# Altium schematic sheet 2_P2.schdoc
size 431 x 309 mm; Symbol: Sheet-Symbol_A3; Device: Sheet-Symbol_A3; @Page Name: P2; @Create Date: 2022-12-06; @Page Count: 3; @Page No: 2; @Project Name: MainBoard; @Schematic Name: Schematic1; @Update Date: 2022-12-29 15:32:21; Company: 嘉立创EDA; Page Size: A3; Version: V1.0
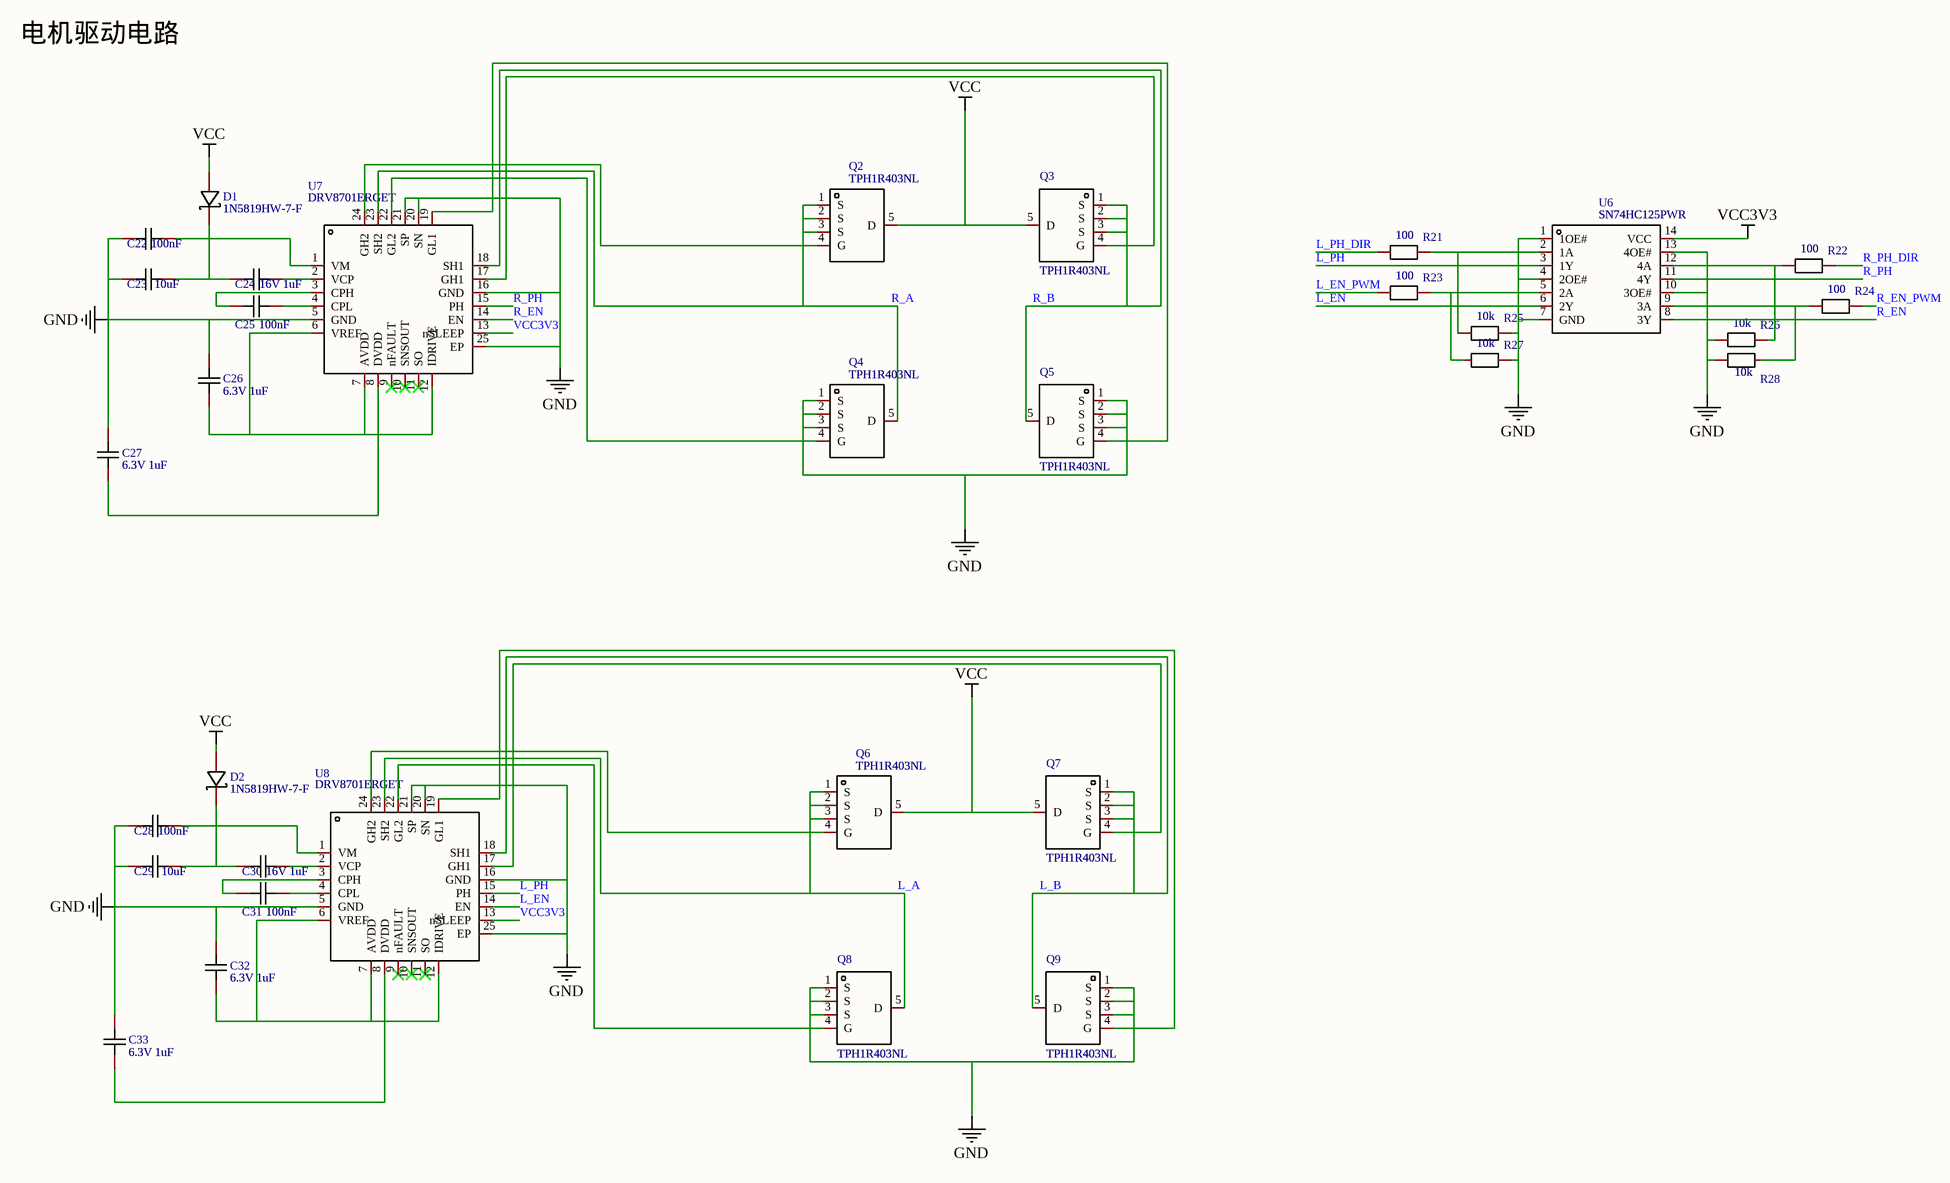
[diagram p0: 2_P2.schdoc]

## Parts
C22  100nF  [C0603]
C23  10uF  [C0603]
C24  16V 1uF  [C0603]
C25  100nF  [C0603]
C26  6.3V 1uF  [C0603]
C27  6.3V 1uF  [C0603]
C28  100nF  [C0603]
C29  10uF  [C0603]
C30  16V 1uF  [C0603]
C31  100nF  [C0603]
C32  6.3V 1uF  [C0603]
C33  6.3V 1uF  [C0603]
D1  1N5819HW-7-F  [SOD-123_L2.8-W1.8-LS3.7-FD]
D2  1N5819HW-7-F  [SOD-123_L2.8-W1.8-LS3.7-FD]
Q2  TPH1R403NL  [POWERVDFN-8_L6.2-W5.2-P1.27-LS6.0-BL]
Q3  TPH1R403NL  [POWERVDFN-8_L6.2-W5.2-P1.27-LS6.0-BL]
Q4  TPH1R403NL  [POWERVDFN-8_L6.2-W5.2-P1.27-LS6.0-BL]
Q5  TPH1R403NL  [POWERVDFN-8_L6.2-W5.2-P1.27-LS6.0-BL]
Q6  TPH1R403NL  [POWERVDFN-8_L6.2-W5.2-P1.27-LS6.0-BL]
Q7  TPH1R403NL  [POWERVDFN-8_L6.2-W5.2-P1.27-LS6.0-BL]
Q8  TPH1R403NL  [POWERVDFN-8_L6.2-W5.2-P1.27-LS6.0-BL]
Q9  TPH1R403NL  [POWERVDFN-8_L6.2-W5.2-P1.27-LS6.0-BL]
R21  100  [R0603]
R22  100  [R0603]
R23  100  [R0603]
R24  100  [R0603]
R25  10k  [R0603]
R26  10k  [R0603]
R27  10k  [R0603]
R28  10k  [R0603]
U6  SN74HC125PWR  [TSSOP-14_L5.0-W4.4-P0.65-LS6.5-BL]
U7  DRV8701ERGET  [VQFN-24_L4.0-W4.0-P0.50-LS4.0-BL-EP]
U8  DRV8701ERGET  [VQFN-24_L4.0-W4.0-P0.50-LS4.0-BL-EP]

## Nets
GND: C22.1 C23.1 C26.2 C27.2 C28.1 C29.1 C32.2 C33.2 Q4.1(S) Q4.2(S) Q4.3(S) Q5.1(S) Q5.2(S) Q5.3(S) Q8.1(S) Q8.2(S) Q8.3(S) Q9.1(S) Q9.2(S) Q9.3(S) R25.2 R26.1 R27.2 R28.1 U6.1(1OE#) U6.4(2OE#) U6.7(GND) U6.10(3OE#) U6.13(4OE#) U7.5(GND) U7.16(GND) U7.20(SN) U7.21(SP) U7.25(EP) U8.5(GND) U8.16(GND) U8.20(SN) U8.21(SP) U8.25(EP)
VCC: D1.1(A) D2.1(A) Q2.5(D) Q3.5(D) Q6.5(D) Q7.5(D)
VCC3V3: U6.14(VCC) U7.13(nSLEEP) U8.13(nSLEEP)
L_A: Q6.1(S) Q6.2(S) Q6.3(S) Q8.5(D) U8.23(SH2)
L_B: Q7.1(S) Q7.2(S) Q7.3(S) Q9.5(D) U8.18(SH1)
L_EN: U6.6(2Y) U8.14(EN)
L_EN_PWM: R23.1
L_PH: U6.3(1Y) U8.15(PH)
L_PH_DIR: R21.1
R_A: Q2.1(S) Q2.2(S) Q2.3(S) Q4.5(D) U7.23(SH2)
R_B: Q3.1(S) Q3.2(S) Q3.3(S) Q5.5(D) U7.18(SH1)
R_EN: U6.8(3Y) U7.14(EN)
R_EN_PWM: R24.2
R_PH: U6.11(4Y) U7.15(PH)
R_PH_DIR: R22.2
NetC22_2: C22.2 C23.2 C24.1 D1.2(K) U7.1(VM)
NetC24_2: C24.2 U7.2(VCP)
NetC25_1: C25.1 U7.3(CPH)
NetC25_2: C25.2 U7.4(CPL)
NetC26_1: C26.1 U7.6(VREF) U7.7(AVDD) U7.12(IDRIVE)
NetC27_1: C27.1 U7.8(DVDD)
NetC28_2: C28.2 C29.2 C30.1 D2.2(K) U8.1(VM)
NetC30_2: C30.2 U8.2(VCP)
NetC31_1: C31.1 U8.3(CPH)
NetC31_2: C31.2 U8.4(CPL)
NetC32_1: C32.1 U8.6(VREF) U8.7(AVDD) U8.12(IDRIVE)
NetC33_1: C33.1 U8.8(DVDD)
NetQ2_4: Q2.4(G) U7.24(GH2)
NetQ3_4: Q3.4(G) U7.17(GH1)
NetQ4_4: Q4.4(G) U7.22(GL2)
NetQ5_4: Q5.4(G) U7.19(GL1)
NetQ6_4: Q6.4(G) U8.24(GH2)
NetQ7_4: Q7.4(G) U8.17(GH1)
NetQ8_4: Q8.4(G) U8.22(GL2)
NetQ9_4: Q9.4(G) U8.19(GL1)
NetR21_2: R21.2 R25.1 U6.2(1A)
NetR22_1: R22.1 R26.2 U6.12(4A)
NetR23_2: R23.2 R27.1 U6.5(2A)
NetR24_1: R24.1 R28.2 U6.9(3A)

Not connected (* = marked no-connect by the designer): U7 9(nFAULT)* 10(SNSOUT)* 11(SO)*; U8 9(nFAULT)* 10(SNSOUT)* 11(SO)*

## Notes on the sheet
- 电机驱动电路

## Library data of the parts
C22 C25 C28 C31 = 100nF: Convert to PCB: yes
C23 C29 = 10uF: Convert to PCB: yes
C24 C30 = 16V 1uF: Convert to PCB: yes
C26 C27 C32 C33 = 6.3V 1uF: Convert to PCB: yes
D1 D2 = 1N5819HW-7-F: Manufacturer: DIODES; Convert to PCB: yes
Q2-Q9 = TPH1R403NL: Manufacturer: TOSHIBA; Convert to PCB: yes
R21-R24 = 100: Convert to PCB: yes
R25-R28 = 10k: Convert to PCB: yes
U6 = SN74HC125PWR: Manufacturer: Texas Instruments; Convert to PCB: yes
U7 U8 = DRV8701ERGET: Manufacturer: TI; Convert to PCB: yes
